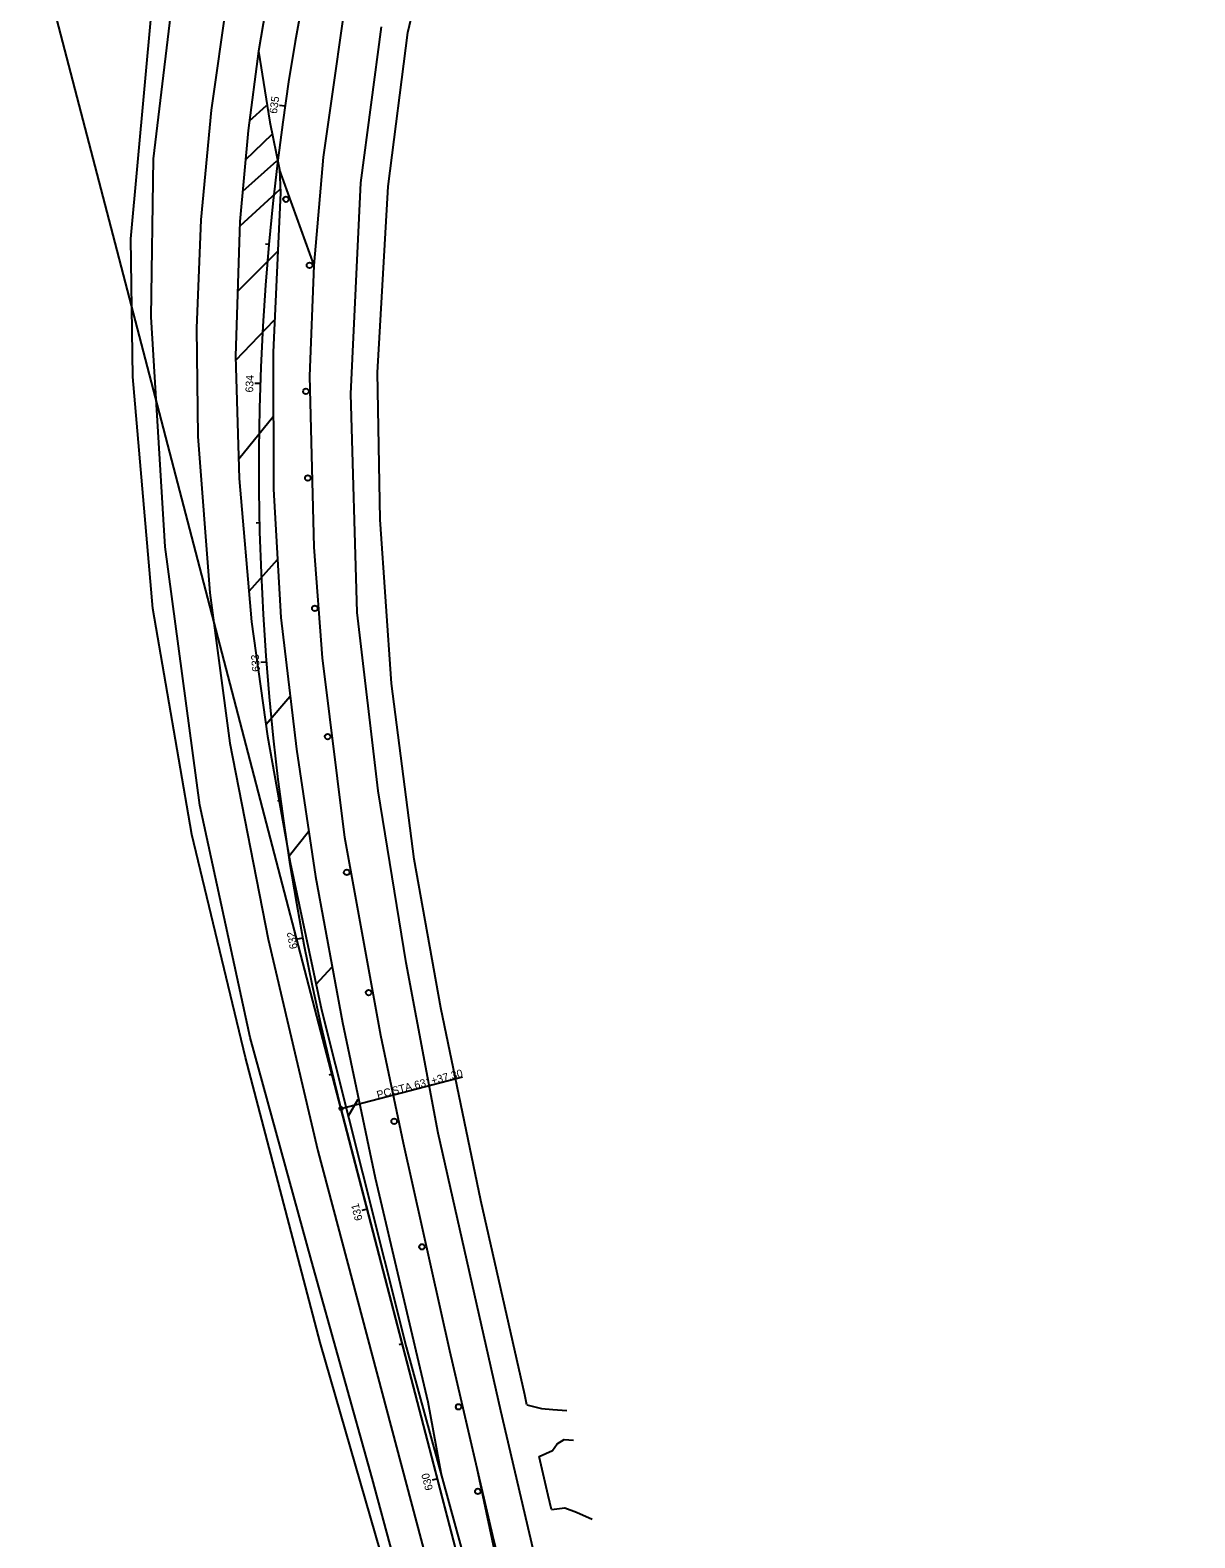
# Model space of a CAD drawing. Extents: x 171274 to 172251, y 454256 to 458569.
# Drawn here: x 171284 to 171702, y 455675 to 456216 of the extents above; entities that cross this region are included whole.
import ezdxf

# ---------------------------------------------------------------- set-up
doc = ezdxf.new("R2010")
doc.units = 0
for name, color, linetype in [('_CIVIL_CONSTRUCTION', 7, 'Continuous'), ('BR_X_Brg_Pad_Object', 7, 'Continuous'), ('BR_X_Gen_Approach_Slab', 7, 'Continuous'), ('BR_X_Rail_Object', 7, 'Continuous'), ('BR_X_Sub_Backwall', 7, 'Continuous'), ('PV_P_Saw_Cut_Line', 7, 'Continuous'), ('PV_X_Walk', 7, 'Continuous'), ('SC_Scratch2', 7, 'Continuous'), ('SC_Scratch4', 7, 'Continuous'), ('UT_X_Water_Cells', 7, 'Continuous'), ('VG_X_Shrub_Line_Lt', 7, 'Continuous')]:
    doc.layers.add(name, color=color, linetype=linetype)

msp = doc.modelspace()

# ---------------------------------------------------------------- linework, layer by layer
at = {"layer": '_CIVIL_CONSTRUCTION'}
for q in [(171283.69, 456257.09), (171395.21, 455829.41)]:
    msp.add_line((171701.51, 454654.7), q, dxfattribs=at)
msp.add_arc((172275.65, 456058.99), 909.89, 134.88472, 194.61425, dxfattribs=at)
msp.add_arc((172275.65, 456058.99), 909.89, 134.88472, 194.61425, dxfattribs=at)
at = {"layer": 'BR_X_Brg_Pad_Object'}
for points in [[(171503.18, 455323.76), (171475.49, 455432.87), (171454.72, 455513.46), (171428.26, 455615.62), (171406.35, 455696.78), (171384.57, 455774.72), (171362.67, 455854.98), (171344.52, 455938.3), (171332.13, 456031.02), (171327.13, 456113.56), (171327.94, 456170.26), (171336.25, 456240.13)], [(171552.92, 455312.25), (171527.2, 455411.62), (171502.46, 455511.52), (171477.38, 455614.49), (171452.58, 455720.96), (171430.11, 455820.63), (171418.58, 455881.68), (171408.49, 455943.41), (171401.05, 456007.44), (171398.69, 456085.97), (171402.37, 456161.63), (171409.79, 456217.67)]]:
    msp.add_lwpolyline(points, dxfattribs=at)
at = {"layer": 'BR_X_Gen_Approach_Slab'}
for points in [[(171372.41, 456249.06), (171365.59, 456208.9), (171361.9, 456180.52), (171358.94, 456147.75), (171357.35, 456099.47), (171358.68, 456055.61), (171363.09, 456004.12), (171368.78, 455963.12), (171376.92, 455917.74), (171388.16, 455864.82), (171402.87, 455806.41), (171418.61, 455743.92), (171438.27, 455671.9), (171450.64, 455624.13), (171463.74, 455573.1), (171476.6, 455521.3), (171489.49, 455470.21), (171501.56, 455421.89), (171512.39, 455380.78), (171524.4, 455333.79)], [(171365.59, 456208.9), (171369.65, 456183.42), (171373.09, 456166.51), (171373.49, 456158.03), (171370.82, 456100.94), (171370.98, 456051.72), (171373.64, 456005.71), (171379.22, 455958.46), (171386.07, 455912.7), (171395.7, 455860.37), (171407.45, 455804.62), (171426.36, 455724.22), (171431.29, 455697.47)]]:
    msp.add_lwpolyline(points, dxfattribs=at)
at = {"layer": 'BR_X_Rail_Object'}
for centre in [(171375.47, 456155.79), (171383.92, 456132.06), (171382.63, 456086.84), (171383.31, 456055.77), (171385.83, 456008.98), (171390.42, 455962.93), (171397.27, 455914.18), (171405.12, 455871.04), (171414.28, 455824.84), (171424.27, 455779.79), (171437.39, 455722.38), (171444.28, 455692.01)]:
    msp.add_circle(centre, 1, dxfattribs=at)
at = {"layer": 'BR_X_Sub_Backwall'}
msp.add_line((171511.85, 455382.07), (171444.08, 455700.27), dxfattribs=at)
msp.add_lwpolyline([(171444.08, 455700.27), (171434.2, 455742.49), (171417.65, 455817.01), (171409.54, 455855.66), (171396.62, 455926.7), (171388.55, 455991.19), (171385.59, 456030.86), (171384.04, 456092.24), (171385.52, 456132), (171373.09, 456166.51)], dxfattribs=at)
at = {"layer": 'PV_P_Saw_Cut_Line'}
for points in [[(171461.92, 455723.14), (171461.11, 455726.64), (171445.31, 455796.47), (171431.02, 455865.63), (171421.47, 455918.95), (171413.26, 455981.96), (171409.27, 456040.86), (171408.32, 456093.56), (171412.13, 456160.37), (171419.13, 456215.58), (171422.03, 456227.81), (171427.08, 456240.66), (171441.08, 456270.63), (171450.32, 456291.63), (171453.6, 456301.97), (171467.65, 456346.3), (171478.59, 456375.6)], [(171558.29, 455107.46), (171557.48, 455110.64), (171540.93, 455172.92), (171510.71, 455286.81), (171486.61, 455378.45), (171470.46, 455441.39), (171454.22, 455507.71), (171429.71, 455601.02), (171414.88, 455651.31), (171387.7, 455745.41), (171360.93, 455847.8), (171341.64, 455927.77), (171327.71, 456008.91), (171320.5, 456092.02), (171319.84, 456141.55), (171327.18, 456222.76), (171334.15, 456270.38), (171334.45, 456271.77)], [(171470.69, 455685.47), (171469.5, 455690.52), (171466.25, 455704.51)]]:
    msp.add_lwpolyline(points, dxfattribs=at)
at = {"layer": 'PV_X_Walk'}
for p, q in [((171362.35, 456183.96), (171368.53, 456189.39)), ((171360.92, 456169.88), (171370.5, 456179.09)), ((171359.95, 456158.72), (171372.2, 456169.53)), ((171358.98, 456146.23), (171373.38, 456159.37)), ((171358.09, 456122.63), (171372.48, 456136.98)), ((171357.42, 456098), (171371.17, 456112.35)), ((171358.57, 456062.57), (171370.81, 456077.84)), ((171362.3, 456015.12), (171372.44, 456026.45)), ((171368.39, 455967.38), (171376.9, 455977.35)), ((171376.63, 455920.14), (171383.58, 455928.81)), ((171386.33, 455874.02), (171392.04, 455880.25)), ((171397.9, 455826.86), (171401.42, 455832.84))]:
    msp.add_line(p, q, dxfattribs=at)
at = {"layer": 'SC_Scratch2'}
for points in [[(171606.9, 456713.08), (171537.84, 456634.83), (171514.38, 456602.92), (171481.72, 456555.36), (171461.08, 456521.63), (171441.58, 456486.99), (171424.04, 456451.38), (171408.15, 456415.38), (171394.36, 456378.7), (171381.63, 456341.12), (171371.07, 456303.24), (171361.56, 456265.59), (171354.26, 456227.23), (171348.62, 456187.8), (171344.87, 456148.4), (171343.42, 456109.47), (171343.88, 456070.6), (171348.16, 456014.58), (171355.27, 455960.53), (171369.03, 455890.22), (171386.9, 455814.22), (171470.04, 455501.07), (171508.5, 455352.39)], [(171472.94, 455579.79), (171449.73, 455676.12), (171434.2, 455742.49), (171417.65, 455817.01), (171409.54, 455855.66), (171396.62, 455926.7), (171388.55, 455991.19), (171385.59, 456030.86), (171384.04, 456092.24), (171385.52, 456132), (171388.97, 456170.87), (171399.27, 456243.93), (171412.62, 456299.43), (171430.57, 456357.84), (171452.53, 456413.92), (171486.74, 456481.97), (171521.83, 456540.12), (171563.53, 456599.56), (171612.4, 456658.42), (171636.48, 456684.91)]]:
    msp.add_lwpolyline(points, dxfattribs=at)
at = {"layer": 'SC_Scratch4'}
msp.add_line((171395.21, 455829.41), (171438.75, 455840.77), dxfattribs=at)
msp.add_circle((171395.21, 455829.41), 0.6, dxfattribs=at)
at = {"layer": 'UT_X_Water_Cells'}
for points in [[(171461.92, 455723.14), (171467.09, 455721.8), (171471.16, 455721.37), (171476.27, 455721.06)], [(171466.25, 455704.51), (171471.06, 455706.71), (171472.81, 455709.13), (171475.21, 455710.62), (171478.61, 455710.41)], [(171470.69, 455685.47), (171475.45, 455686.09), (171479.63, 455684.53), (171485.36, 455682.08)]]:
    msp.add_lwpolyline(points, dxfattribs=at)
at = {"layer": 'VG_X_Shrub_Line_Lt'}
for p, q in [((171375.13, 456189.16), (171373.15, 456189.45)), ((171369.34, 456139.5), (171368.14, 456139.61)), ((171366.28, 456089.6), (171364.29, 456089.67)), ((171365.98, 456039.61), (171364.78, 456039.58)), ((171368.41, 455989.67), (171366.42, 455989.52)), ((171373.59, 455939.95), (171372.4, 455939.79)), ((171381.49, 455890.58), (171379.52, 455890.21)), ((171392.09, 455841.73), (171390.92, 455841.44)), ((171404.62, 455793.32), (171402.68, 455792.82)), ((171417.23, 455744.94), (171416.07, 455744.64)), ((171429.85, 455696.56), (171427.91, 455696.05))]:
    msp.add_line(p, q, dxfattribs=at)

# ---------------------------------------------------------------- texts
at = {"layer": 'SC_Scratch4'}
for s, p in [('631+37.30', (171421.89, 455836.41)), (' STA. ', (171412.87, 455834.06)), ('PC', (171408.42, 455832.9))]:
    msp.add_text(s, height=2.8, rotation=14.6143, dxfattribs=at).set_placement(p)
at = {"layer": 'VG_X_Shrub_Line_Lt'}
for s, rotation, p in [('635', 81.7748, (171372.2, 456186.34)), ('634', 88.0718, (171363.68, 456086.41)), ('633', 94.3689, (171366.16, 455986.3)), ('632', 100.6659, (171379.63, 455886.97)), ('631', 104.6143, (171403.01, 455789.57)), ('630', 104.6143, (171428.25, 455692.77))]:
    msp.add_text(s, height=2.8, rotation=rotation, dxfattribs=at).set_placement(p)

doc.saveas('drawing.dxf')
